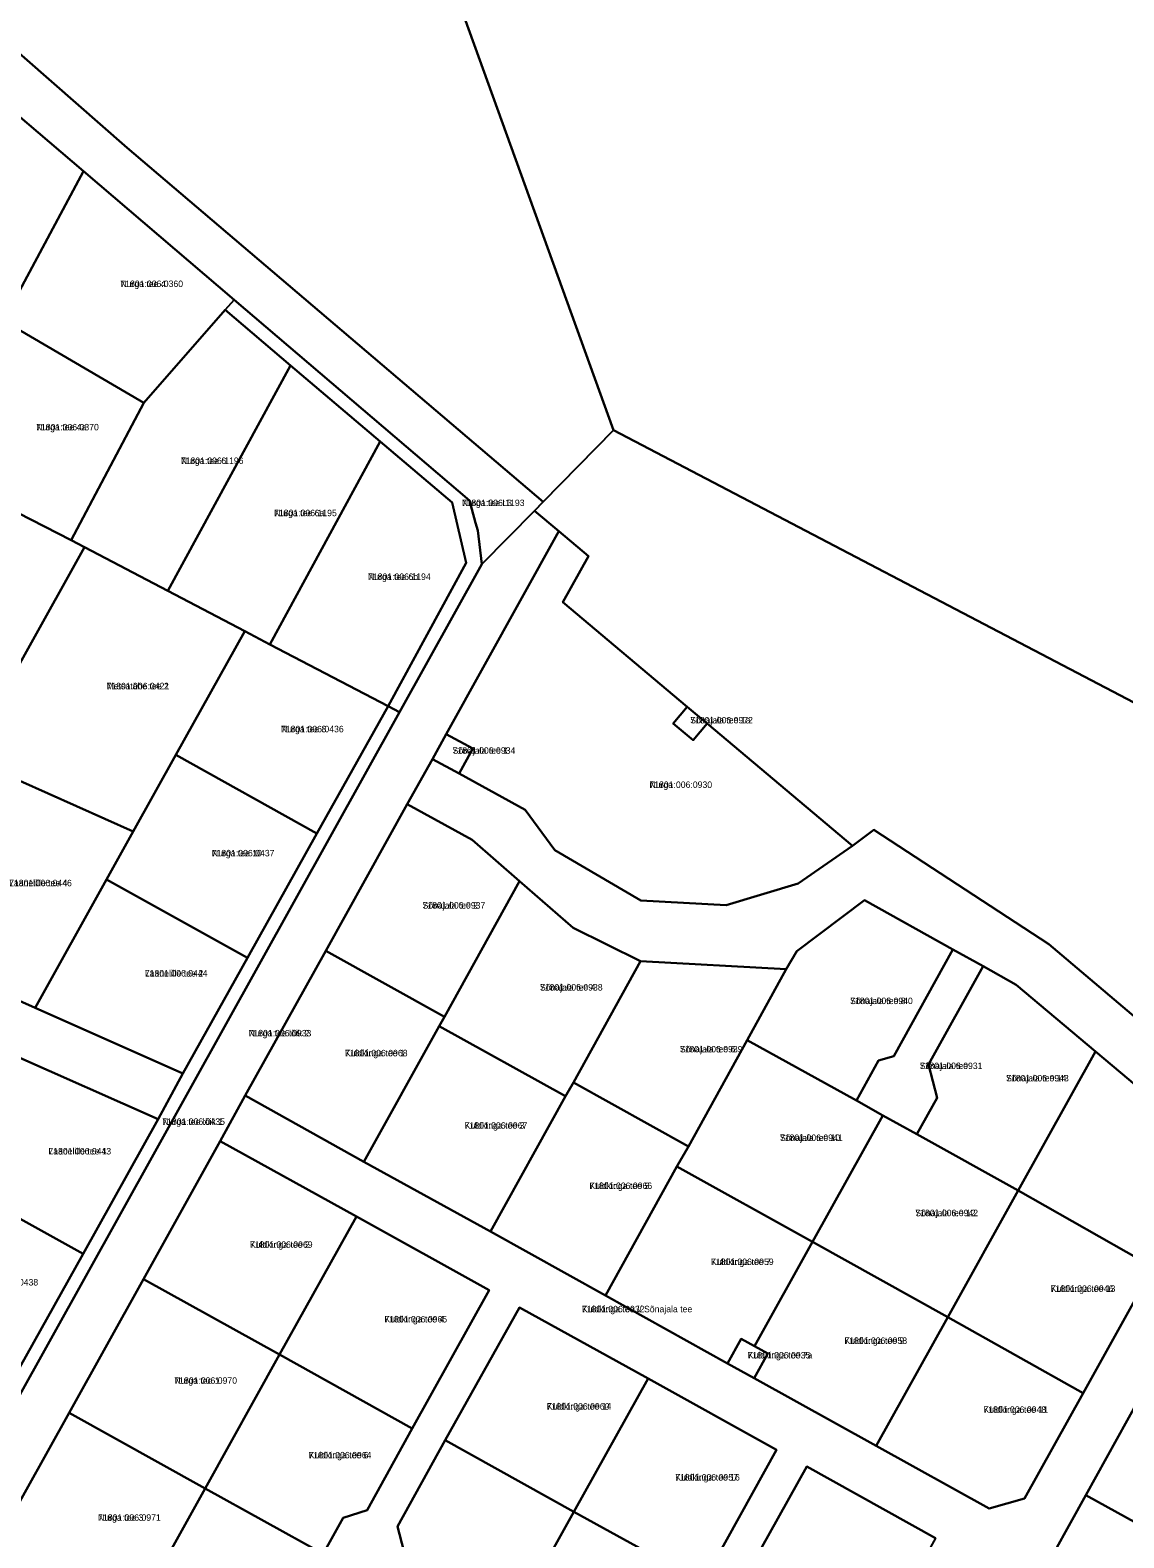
# Model space of a CAD drawing. Extents: x 529768 to 552006, y 6562269 to 6580975.
# Drawn here: x 538365.3 to 538618.3, y 6569572.9 to 6569921.8 of the extents above; entities that cross this region are included whole.
import ezdxf

# ---------------------------------------------------------------- set-up
doc = ezdxf.new("R2010")
doc.units = 0
for name, color, linetype in [('L_AADRESS', 7, 'Continuous'), ('PIIR', 7, 'Continuous'), ('TUNNUS', 7, 'Continuous')]:
    doc.layers.add(name, color=color, linetype=linetype)

msp = doc.modelspace()

# ---------------------------------------------------------------- linework, layer by layer
at = {"layer": 'PIIR'}
for points in [[(538194.78, 6570045.29), (538204.09, 6570052.49), (538294.54, 6569976.3), (538387.81, 6569894.55), (538483.98, 6569812.62), (538481.98, 6569810.6), (538469.84, 6569798.25), (538468.86, 6569806.04), (538468.33, 6569807.76), (538466.92, 6569812.96), (538412.51, 6569859.39), (538377.69, 6569889.12), (538326.28, 6569933.03), (538292.44, 6569961.91), (538270.33, 6569980.79), (538256.38, 6569992.7), (538223.22, 6570021.01)], [(538345.46, 6569888.38), (538317.02, 6569913.66), (538315.93, 6569914.67), (538326.28, 6569933.03), (538377.69, 6569889.14), (538361.67, 6569859.15), (538336.78, 6569872.31)], [(538361.67, 6569859.15), (538377.69, 6569889.14), (538412.51, 6569859.39), (538410.45, 6569857.04), (538391.66, 6569835.55), (538359.11, 6569854.57)], [(538412.51, 6569859.39), (538466.92, 6569812.96), (538468.33, 6569807.76), (538468.86, 6569806.04), (538469.84, 6569798.25), (538450.76, 6569763.95), (538448.11, 6569765.36), (538466.16, 6569798.57), (538462.93, 6569812.46), (538446.31, 6569826.58), (538425.56, 6569844.2), (538410.45, 6569857.04)], [(538351.09, 6569840.13), (538359.11, 6569854.57), (538391.66, 6569835.55), (538374.81, 6569803.78), (538340.87, 6569821.17)], [(538410.45, 6569857.04), (538425.56, 6569844.2), (538397.21, 6569792.04), (538377.9, 6569802.16), (538374.81, 6569803.78), (538391.66, 6569835.55)], [(538425.56, 6569844.2), (538446.31, 6569826.58), (538420.8, 6569779.68), (538414.99, 6569782.72), (538397.21, 6569792.04)], [(538446.31, 6569826.58), (538462.93, 6569812.46), (538466.16, 6569798.57), (538448.11, 6569765.36), (538420.8, 6569779.68)], [(538500.26, 6569829.22), (538627.25, 6569762.75), (538663.61, 6569744.7), (538720.63, 6569712.89), (538685.47, 6569642.49), (538683.29, 6569643.7), (538681.29, 6569645.18), (538660.49, 6569660.54), (538662.22, 6569662.89), (538654.95, 6569668.21), (538653.32, 6569665.98), (538600.95, 6569710.31), (538560.45, 6569736.74), (538555.57, 6569733.07), (538521.9, 6569761.37), (538517.31, 6569765.23), (538488.53, 6569789.42), (538494.46, 6569800.11), (538487.63, 6569805.85), (538481.98, 6569810.6), (538483.98, 6569812.62)], [(538340.87, 6569821.17), (538374.81, 6569803.78), (538377.9, 6569802.16), (538351.04, 6569753.92), (538345.8, 6569756.83), (538339.96, 6569746.35), (538310.01, 6569763.02), (538331.25, 6569802.37)], [(538481.98, 6569810.6), (538487.63, 6569805.85), (538461.57, 6569758.92), (538458.39, 6569753.08), (538452.57, 6569742.7), (538433.7, 6569708.78), (538415.11, 6569675.33), (538409.28, 6569664.76), (538391.55, 6569632.83), (538374.35, 6569601.84), (538359.18, 6569574.54), (538356.27, 6569569.3), (538353.57, 6569570.8), (538344.1, 6569572.28), (538345.65, 6569575.1), (538450.76, 6569763.95), (538469.84, 6569798.25)], [(538487.63, 6569805.85), (538494.46, 6569800.11), (538488.53, 6569789.42), (538517.31, 6569765.23), (538514.09, 6569761.4), (538518.69, 6569757.54), (538521.9, 6569761.37), (538555.57, 6569733.07), (538542.95, 6569724.35), (538526.29, 6569719.34), (538506.6, 6569720.44), (538486.66, 6569732.02), (538479.84, 6569741.35), (538464.53, 6569749.79), (538467.69, 6569755.58), (538461.57, 6569758.92)], [(538377.9, 6569802.16), (538397.21, 6569792.04), (538414.99, 6569782.72), (538399.06, 6569754.1), (538389.18, 6569736.34), (538356.29, 6569751), (538351.04, 6569753.92)], [(538414.99, 6569782.72), (538420.8, 6569779.68), (538448.11, 6569765.36), (538431.68, 6569735.94), (538399.06, 6569754.1)], [(538448.11, 6569765.36), (538450.76, 6569763.95), (538345.65, 6569575.1), (538344.1, 6569572.28), (538341.05, 6569573.02), (538342.38, 6569575.61), (538359.59, 6569606.32), (538377.59, 6569638.65), (538394.92, 6569669.8), (538400.66, 6569680.38), (538415.6, 6569707.13), (538431.68, 6569735.94)], [(538517.31, 6569765.23), (538521.9, 6569761.37), (538518.69, 6569757.54), (538514.09, 6569761.4)], [(538264.26, 6569739.51), (538316.37, 6569716.29), (538323.7, 6569713.02), (538326.63, 6569718.29), (538341.71, 6569745.38), (538339.96, 6569746.35), (538345.8, 6569756.83), (538351.04, 6569753.92), (538356.29, 6569751), (538350.45, 6569740.51), (538348.7, 6569741.49), (538331.77, 6569711.07), (538366.5, 6569695.6), (538400.66, 6569680.38), (538394.92, 6569669.8), (538361.56, 6569684.66), (538327.06, 6569700.03), (538317.43, 6569704.32), (538276.16, 6569722.71), (538269.78, 6569725.55), (538267.89, 6569724.75), (538255.8, 6569730.14), (538260.66, 6569732.9), (538262.76, 6569736.8)], [(538461.57, 6569758.92), (538467.69, 6569755.58), (538464.53, 6569749.79), (538458.39, 6569753.08)], [(538399.06, 6569754.1), (538431.68, 6569735.94), (538415.6, 6569707.13), (538383.01, 6569725.26), (538389.18, 6569736.34)], [(538356.29, 6569751), (538389.18, 6569736.34), (538383.01, 6569725.26), (538366.5, 6569695.6), (538331.77, 6569711.07), (538348.7, 6569741.49), (538350.45, 6569740.51)], [(538452.57, 6569742.7), (538467.59, 6569734.43), (538478.49, 6569724.85), (538461.15, 6569693.51), (538433.7, 6569708.78)], [(538383.01, 6569725.26), (538415.6, 6569707.13), (538400.66, 6569680.38), (538366.5, 6569695.6)], [(538478.49, 6569724.85), (538490.92, 6569714.09), (538506.52, 6569706.41), (538491.01, 6569678.32), (538489.16, 6569675.13), (538459.98, 6569691.36), (538461.15, 6569693.51)], [(538558.28, 6569720.45), (538578.77, 6569709.07), (538565.07, 6569684.39), (538561.59, 6569683.39), (538556.43, 6569674.1), (538531.19, 6569688.11), (538540.22, 6569704.49), (538542.63, 6569708.69)], [(538433.7, 6569708.78), (538461.15, 6569693.51), (538459.98, 6569691.36), (538442.5, 6569659.96), (538415.11, 6569675.33)], [(538578.77, 6569709.07), (538585.77, 6569705.18), (538573.14, 6569682.44), (538575.09, 6569674.75), (538570.41, 6569666.33), (538562.54, 6569670.7), (538556.43, 6569674.1), (538561.59, 6569683.39), (538565.07, 6569684.39)], [(538506.52, 6569706.41), (538540.22, 6569704.49), (538531.19, 6569688.11), (538517.58, 6569663.53), (538491.01, 6569678.32)], [(538585.77, 6569705.18), (538593.42, 6569700.93), (538611.72, 6569685.44), (538593.87, 6569653.3), (538570.41, 6569666.33), (538575.09, 6569674.75), (538573.14, 6569682.44)], [(538459.98, 6569691.36), (538489.16, 6569675.13), (538471.82, 6569643.82), (538442.5, 6569659.96)], [(538531.19, 6569688.11), (538556.43, 6569674.1), (538562.54, 6569670.7), (538546.28, 6569641.43), (538514.94, 6569658.84), (538517.58, 6569663.53)], [(538361.56, 6569684.66), (538394.92, 6569669.8), (538377.59, 6569638.65), (538345.8, 6569656.34)], [(538611.72, 6569685.44), (538639.7, 6569661.93), (538625.07, 6569635.57), (538593.87, 6569653.3)], [(538491.01, 6569678.32), (538517.58, 6569663.53), (538514.94, 6569658.84), (538498.38, 6569629.01), (538471.82, 6569643.82), (538489.16, 6569675.13)], [(538562.54, 6569670.7), (538570.41, 6569666.33), (538593.87, 6569653.3), (538577.62, 6569624.03), (538546.28, 6569641.43)], [(538409.28, 6569664.76), (538440.8, 6569647.3), (538423.03, 6569615.35), (538391.55, 6569632.83)], [(538514.94, 6569658.84), (538546.28, 6569641.43), (538532.87, 6569617.29), (538529.81, 6569618.99), (538526.66, 6569613.31), (538498.38, 6569629.01)], [(538345.8, 6569656.34), (538377.59, 6569638.65), (538359.59, 6569606.32), (538327.8, 6569624.01), (538337.53, 6569641.48)], [(538593.87, 6569653.3), (538625.07, 6569635.57), (538608.88, 6569606.42), (538577.62, 6569624.03)], [(538440.8, 6569647.3), (538471.52, 6569630.25), (538453.72, 6569598.26), (538423.03, 6569615.35)], [(538546.28, 6569641.43), (538577.62, 6569624.03), (538561.05, 6569594.21), (538532.78, 6569609.91), (538535.93, 6569615.59), (538532.87, 6569617.29)], [(538391.55, 6569632.83), (538423.03, 6569615.35), (538405.82, 6569584.36), (538374.35, 6569601.84)], [(538478.51, 6569626.24), (538508.28, 6569609.8), (538491.1, 6569578.96), (538461.35, 6569595.52)], [(538577.62, 6569624.03), (538608.88, 6569606.42), (538595.34, 6569582.04), (538587.17, 6569579.7), (538561.05, 6569594.21)], [(538529.81, 6569618.99), (538532.87, 6569617.29), (538535.93, 6569615.59), (538532.78, 6569609.91), (538526.66, 6569613.31)], [(538628.66, 6569617.35), (538655.48, 6569602.4), (538658.79, 6569600.55), (538639.62, 6569566.14), (538635.45, 6569568.45), (538609.51, 6569582.85)], [(538423.03, 6569615.35), (538453.72, 6569598.26), (538443.26, 6569579.33), (538437.7, 6569577.56), (538433.08, 6569569.23), (538405.82, 6569584.36)], [(538508.28, 6569609.8), (538537.96, 6569593.31), (538520.91, 6569562.56), (538491.1, 6569578.96)], [(538374.35, 6569601.84), (538405.82, 6569584.36), (538390.33, 6569556.47), (538387.81, 6569551.93), (538356.27, 6569569.3), (538359.18, 6569574.54)], [(538461.35, 6569595.52), (538491.1, 6569578.96), (538473.29, 6569546.9), (538447.06, 6569561.46), (538451.76, 6569569.92), (538450.32, 6569575.57)], [(538544.95, 6569589.43), (538574.76, 6569572.87), (538557.67, 6569542.1), (538527.85, 6569558.75)], [(538405.82, 6569584.36), (538433.08, 6569569.23), (538440.08, 6569565.34), (538424.49, 6569537.27), (538422.13, 6569533.02), (538387.81, 6569551.93), (538390.33, 6569556.47)], [(538609.51, 6569582.85), (538635.45, 6569568.45), (538639.62, 6569566.14), (538618.11, 6569527.45), (538613.6, 6569529.95), (538598.04, 6569538.57), (538598.46, 6569562.95)], [(538491.1, 6569578.96), (538520.91, 6569562.56), (538509.7, 6569542.43), (538504.14, 6569540.66), (538499.52, 6569532.33), (538473.29, 6569546.9)]]:
    msp.add_lwpolyline(points, close=True, dxfattribs=at)
for points in [[(538769.82, 6570046.94), (538826.28, 6569871.99), (538622.31, 6569849.39), (538627.25, 6569762.75), (538500.26, 6569829.22), (538463.69, 6569930.51)], [(538463.69, 6569930.51), (538500.26, 6569829.22), (538483.98, 6569812.62), (538387.81, 6569894.55), (538294.54, 6569976.3)], [(538639.7, 6569661.93), (538611.72, 6569685.44), (538593.42, 6569700.93), (538585.77, 6569705.18), (538578.77, 6569709.07), (538558.28, 6569720.45), (538542.63, 6569708.69), (538540.22, 6569704.49), (538506.52, 6569706.41), (538490.92, 6569714.09), (538478.49, 6569724.85), (538467.59, 6569734.43), (538452.57, 6569742.7), (538458.39, 6569753.08), (538464.53, 6569749.79), (538479.84, 6569741.35), (538486.66, 6569732.02), (538506.6, 6569720.44), (538526.29, 6569719.34), (538542.95, 6569724.35), (538555.57, 6569733.07), (538560.45, 6569736.74), (538600.95, 6569710.31), (538653.32, 6569665.98)], [(538433.08, 6569569.23), (538437.7, 6569577.56), (538443.26, 6569579.33), (538453.72, 6569598.26), (538471.52, 6569630.25), (538440.8, 6569647.3), (538409.28, 6569664.76), (538415.11, 6569675.33), (538442.5, 6569659.96), (538471.82, 6569643.82), (538498.38, 6569629.01), (538526.66, 6569613.31), (538532.78, 6569609.91), (538561.05, 6569594.21), (538587.17, 6569579.7), (538595.34, 6569582.04), (538608.88, 6569606.42), (538625.07, 6569635.57)], [(538520.91, 6569562.56), (538537.96, 6569593.31), (538508.28, 6569609.8), (538478.51, 6569626.24), (538461.35, 6569595.52), (538450.32, 6569575.57), (538451.76, 6569569.92)], [(538628.66, 6569617.35), (538609.51, 6569582.85), (538598.46, 6569562.95)], [(538574.76, 6569572.87), (538544.95, 6569589.43), (538527.85, 6569558.75)]]:
    msp.add_lwpolyline(points, dxfattribs=at)

# ---------------------------------------------------------------- texts
at = {"layer": 'L_AADRESS'}
for s, p in [('Nurga tee 4', (538386.21, 6569862.35)), ('Nurga tee 4a', (538366.73, 6569829.18)), ('Nurga tee 6', (538400.19, 6569821.41)), ('Nurga tee L3', (538465.19, 6569811.67)), ('Nurga tee 6a', (538421.76, 6569809.33)), ('Nurga tee 6b', (538443.48, 6569794.58)), ('Metsatähe tee 2', (538383.02, 6569769.28)), ('Nurga tee 8', (538423.36, 6569759.33)), ('Sõnajala tee 1a', (538518, 6569761.38)), ('Sõnajala tee 1', (538463.05, 6569754.36)), ('Nurga', (538508.57, 6569746.45)), ('Nurga tee 10', (538407.35, 6569730.62)), ('Laanelille tee 4', (538360.48, 6569723.71)), ('Sõnajala tee 2', (538456.1, 6569718.54)), ('Laanelille tee 2', (538391.86, 6569702.82)), ('Sõnajala tee 4', (538483.25, 6569699.57)), ('Sõnajala tee 8', (538554.98, 6569696.44)), ('Nurga tee lõik 2', (538415.87, 6569688.97)), ('Sõnajala tee 6', (538515.61, 6569685.26)), ('Kuldkinga tee 1', (538438.13, 6569684.36)), ('Sõnajala tee', (538571.1, 6569681.41)), ('Sõnajala tee 14', (538591.06, 6569678.55)), ('Nurga tee lõik 1', (538395.9, 6569668.5)), ('Kuldkinga tee 3', (538465.83, 6569667.61)), ('Sõnajala tee 10', (538538.76, 6569664.77)), ('Laanelille tee 1', (538369.57, 6569661.65)), ('Kuldkinga tee 5', (538494.7, 6569653.66)), ('Sõnajala tee 12', (538570.08, 6569647.37)), ('Kuldkinga tee 2', (538416.17, 6569640.05)), ('Kuldkinga tee 7', (538522.8, 6569636.07)), ('Kuldkinga tee 13', (538601.38, 6569629.86)), ('Kuldkinga tee 4', (538447.28, 6569622.78)), ('Kuldkinga tee // Sõnajala tee', (538492.94, 6569625.13)), ('Kuldkinga tee 9', (538553.67, 6569617.82)), ('Kuldkinga tee 7a', (538531.29, 6569614.45)), ('Nurga tee 1', (538398.69, 6569608.59)), ('Kuldkinga tee 14', (538484.82, 6569602.61)), ('Kuldkinga tee 11', (538585.83, 6569601.87)), ('Kuldkinga tee 6', (538429.77, 6569591.33)), ('Kuldkinga tee 16', (538514.53, 6569586.2)), ('Nurga tee 3', (538381.05, 6569576.89))]:
    msp.add_text(s, height=1.5, dxfattribs=at).set_placement(p)
at = {"layer": 'TUNNUS'}
for s, p in [('71801:006:0360', (538386.21, 6569862.35)), ('71801:006:0370', (538366.73, 6569829.18)), ('71801:006:1196', (538400.19, 6569821.41)), ('71801:006:1193', (538465.19, 6569811.67)), ('71801:006:1195', (538421.76, 6569809.33)), ('71801:006:1194', (538443.48, 6569794.58)), ('71801:006:0421', (538383.02, 6569769.28)), ('71801:006:0436', (538423.36, 6569759.33)), ('71801:006:0972', (538518, 6569761.38)), ('71801:006:0934', (538463.05, 6569754.36)), ('71801:006:0930', (538508.57, 6569746.45)), ('71801:006:0437', (538407.35, 6569730.62)), ('71801:006:0446', (538360.48, 6569723.71)), ('71801:006:0937', (538456.1, 6569718.54)), ('71801:006:0444', (538391.86, 6569702.82)), ('71801:006:0938', (538483.25, 6569699.57)), ('71801:006:0940', (538554.98, 6569696.44)), ('71801:006:0933', (538415.87, 6569688.97)), ('71801:006:0939', (538515.61, 6569685.26)), ('71801:006:0968', (538438.13, 6569684.36)), ('71801:006:0931', (538571.1, 6569681.41)), ('71801:006:0943', (538591.06, 6569678.55)), ('71801:006:0435', (538395.9, 6569668.5)), ('71801:006:0967', (538465.83, 6569667.61)), ('71801:006:0941', (538538.76, 6569664.77)), ('71801:006:0443', (538369.57, 6569661.65)), ('71801:006:0966', (538494.7, 6569653.66)), ('71801:006:0942', (538570.08, 6569647.37)), ('71801:006:0969', (538416.17, 6569640.05)), ('71801:006:0959', (538522.8, 6569636.07)), ('71801:006:0438', (538352.7, 6569631.33)), ('71801:006:0946', (538601.38, 6569629.86)), ('71801:006:0965', (538447.28, 6569622.78)), ('71801:006:0932', (538492.94, 6569625.13)), ('71801:006:0958', (538553.67, 6569617.82)), ('71801:006:0935', (538531.29, 6569614.45)), ('71801:006:0970', (538398.69, 6569608.59)), ('71801:006:0960', (538484.82, 6569602.61)), ('71801:006:0948', (538585.83, 6569601.87)), ('71801:006:0964', (538429.77, 6569591.33)), ('71801:006:0957', (538514.53, 6569586.2)), ('71801:006:0971', (538381.05, 6569576.89))]:
    msp.add_text(s, height=1.5, dxfattribs=at).set_placement(p)

doc.saveas('drawing.dxf')
